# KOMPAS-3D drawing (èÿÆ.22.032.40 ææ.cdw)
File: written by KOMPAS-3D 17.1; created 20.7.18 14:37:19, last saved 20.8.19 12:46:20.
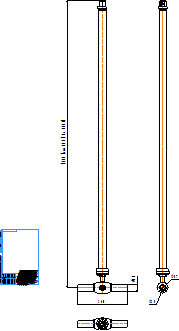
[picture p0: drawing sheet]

Sheet 1: A4, portrait

Title block, sheet 1: name: КШТ.22.032.40 С/С; sheets: 1; sheet format: A4; stored path: C:\Users\kka\KOMPAS_Work\Модели кранов для исследований\DN32\С удлинением\КШТ.22.032.40 СС.cdw

Referenced files in C:\Users\kka\KOMPAS_Work\Модели кранов для исследований\DN32\: АПТА.0203-1219.04.01 _ Корпус крана Ду32 (Труба по ГОСТ).m3d, АПТА.0203-1018.04.02 _ Корпус штока Ду10-32.m3d, АПТА.0203-2611.04.02 _ Шток Ду32.m3d, АПТА.0203-2611.00.01 _ Шар Ду32.m3d, АПТА.0203-1018.01.02 _ Подкладка для кольца Ду10-32.m3d, АПТА.0203-1018.04.04 _ Шайба фрикционная Ду10-32.m3d, АПТА.0203-1018.01.01 _ Кольцо прокладочное Ду10-32.m3d, Кольцо Viton 10.3x2.4.m3d, Кольцо EPDM 10.3x2.4.m3d, АПТА.0203-1219.00.00 _ Кран шаровой сварной Ду32 (труба по ГОСТ).a3d!АПТА.0203-1219.00.00!Деталь (локальная).m3d, АПТА.0203-1219.03.01 _ Патрубок сварной точенный Ду32 (труба по ГОСТ).m3d, АПТА.0203-2611.02.05 _ Уплотнение седловое Ду32.m3d, АПТА.0203-2611.02.04 _ Кольцо опорное Ду32.m3d, АПТА.0203-2611.02.03 _ Пружина тарельчатая Ду32.m3d, АПТА.0203-2611.02.02 _ Кольцо горловое Ду32.m3d, АПТА.0203-1219.00.00 _ Кран шаровой сварной Ду32 (труба по ГОСТ).a3d!АПТА.0203-1219.00.00!Деталь (локальная) 1.m3d, ручка15-32.m3d, АПТА.0203-1018.03.00 _ Ручка Ду10-32.a3d, АПТА.0203-1219.00.00 _ Кран шаровой сварной Ду32 (труба по ГОСТ).a3d
Referenced files in C:\Program Files\ASCON\KOMPAS-3D v17\Libs\PartLib\DATA\VAULT\methods\kompas\3d\: PLib_Pin_3128_712.m3d, PLib_Blind_Nut_type1_900.m3d, PLib_Bolt_1_900.m3d, PLib_Washer_2_712.m3d, PLib_Pins_GOST_14229_911.m3d, PLib_Screw_GOST_8878-84_900.m3d
Referenced files in C:\Users\kka\KOMPAS_Work\КШ удлиненные ПП МОСФЛОУЛАЙН ф. ADL\DN25ПП\: ухватка15-32.m3d
Referenced files in C:\Users\kka\KOMPAS_Work\Удлинения БИВАЛ ф. ADL\Небюджет\Специальные ISO фланцы\: Фланец Ду15-32.m3d
Referenced files in C:\Users\kka\KOMPAS_Work\Удлинения БИВАЛ ф. ADL\Небюджет\Удлинения_2010\УШДн15-32\: УШ.251.00.03 _ Фланец нижний.m3d, УШ.251.00.07 _ Прокладка Ду20-50.m3d, УШ.251.00.05 _ Шток удлинителя Ду20-50.m3d, УШ.251.00.04 _ Гайка 32.m3d, УШ.251.00.01 _ Крышка удлинения.m3d, УШ.251.00.06 _ Тело удлинителя Ду20-50.m3d, УШ.251.00.08 _ Адаптер Ду20-32.m3d, УШ.251.00.00 _ Удлинение штока Ду20-32.a3d!УШ.251.00.00!Деталь (локальная).m3d, АПТА.0203-2617.11.03 - Кольцо прокладочное Ду65-80.m3d, УШ.251.00.00 _ Удлинение штока Ду20-32.a3d!УШ.251.00.00!Деталь (локальная) 1.m3d, УШ.251.00.00 _ Удлинение штока Ду20-32.a3d
Referenced files in C:\Users\kka\KOMPAS_Work\Модели кранов для исследований\DN80\: Кольцо EPDM 19.2x3.m3d
Referenced files in C:\Users\kka\KOMPAS_Work\Модели кранов для исследований\DN32\С удлинением\: КШТ.22.032.40 СС.a3d
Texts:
  kka
  adl
  Рама для чертежей
  Лит-Масса-Масштаб
  Материал-Предприятие
  Масштаб
  Изм.
  Лист
  № докум.
  Подп.
  Дата
  Лит.
  Разраб.
  Пров.
  Т.контр.
  Листов
  Внимание! Данный продукт является объектом авторского права ООО «Торговый Дом АДЛ».
  Запрещается изменение, копирование, распространение
  (в том числе путем копирования на другие сайты и ресурсы в Интернете)
  или любое иное использование информации и объектов без предварительного
  согласия правообладателя (ООО «Торговый Дом АДЛ»).
  Н.контр.
  Утв.
  ООО "Торговый дом АДЛ"
  Изменение
  Номер документа
  Подпись
  Обозначение документа
  Наименование изделия
  Масса изделия по ГОСТ 2.109-73
  Порядковый номер листа
  Общее количество листов в документе
  Характер работы, выполненной лицом, подписавшим документ
  Наименование или индекс предприятия, выпускающего документ
  Инв. № подл.
  Подп. и дата
  Взам. инв. №
  Инв. № дубл.
  Инвентарный номер подлинника по ГОСТ 2.501-68
  Подпись принявшего подлинник в отдел технической документации
  Инвентарный номер подлинника, взамен которого выпущен данный подлинник
  Инвентарный номер дубликата по ГОСТ 2.502-68
  Подпись принявшего дубликат в отдел технической документации
  Справ. №
  Перв. примен.
  Обозначение документа, взамен или на основании которого выпущен данный документ
  Обозначение документа, в котором впервые записан данный документ
  Подпись лица, копировавшего чертеж
  Обозначение формата листа
  !Рама для чертежа
  Корпус крана Ду32 (Труба по ГОСТ)
  АПТА.0203-1219.04.01
  Корпус штока Ду10-32 (исполнение 2)
  АПТА.0203-1018.04.02
  Шток Ду32
  АПТА.0203-2611.04.02
  Шар Ду32
  АПТА.0203-2611.00.01
  Подкладка для кольца Ду10-32
  АПТА.0203-1018.01.02
  Шайба фрикционная Ду10-32
  АПТА.0203-1018.04.04
  Кольцо прокладочное Ду10-32
  АПТА.0203-1018.01.01
  Кольцо Viton 10.3x2.4
  Кольцо EPDM 10.3x2.4
  Штифт 2.3x24 ГОСТ 3128-70
  Деталь (локальная)
  Патрубок сварной точенный Ду32 (труба по ГОСТ)
  АПТА.0203-1219.03.01
  Уплотнение седловое Ду32
  АПТА.0203-2611.02.05
  Кольцо опорное Ду32
  АПТА.0203-2611.02.04
  Пружина тарельчатая Ду32
  АПТА.0203-2611.02.03
  Кольцо горловое Ду32
  АПТА.0203-2611.02.02
  ручка15-32
  ухватка15-32
  Ручка Ду10-32
  АПТА.0203-1018.03.00
  Гайка М10-6H.04.019 ГОСТ 11860-85
  Присоединительный ISO фланец Ду15-32
  ФС.1532.00.01
  Кран шаровой сварной Ду32 (труба по ГОСТ)
  АПТА.0203-1219.00.00
  Фланец нижний
  УШ.251.00.03
  Прокладка Ду20-50
  УШ.251.00.07
  Шток удлинителя Ду20-50
  УШ.251.00.05
  Гайка 32
  УШ.251.00.04
  Крышка корпуса Ду15-32
  УШ.251.00.01
  Тело удлинителя Ду20-50
  УШ.251.00.06
  Адаптер Ду20-32
  УШ.251.00.08
  Корпус
  Болт М6-6gx25 ГОСТ 7805-70
  Шайба 6 65Г 019 ГОСТ 6402-70
  Штифт A.8x12 ГОСТ 14229-93
  Штифт A.8x30 ГОСТ 14229-93
  Кольцо прокладочное Ду65-80
  АПТА.0203-2617.11.03
  Кольцо EPDM 19.2x3
  Винт М4-6gx6.14H.019 ГОСТ 8878-93
  Удлинение штока Ду20-32
  УШ.251.00.00
  Штифт 2.3x14 ГОСТ 3128-70
Dimensions and other numbers on the sheet: 1:1; 1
